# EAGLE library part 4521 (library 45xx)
24-stage FREQUENCY DIVIDER
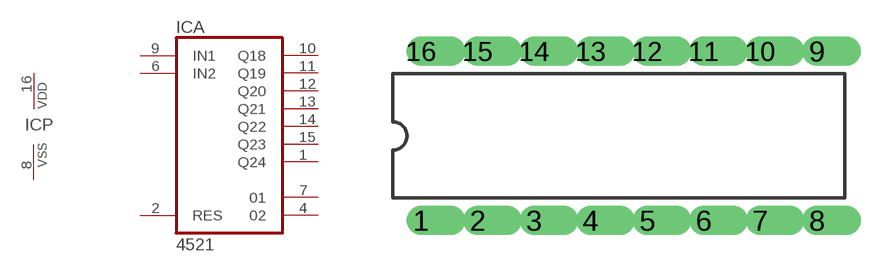
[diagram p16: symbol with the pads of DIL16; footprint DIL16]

Designator prefix IC; gates A=4521 P=PWRN

## 4521N  [DIL16]
1  A:Q24  out
2  A:RES  in
4  A:02  out
6  A:IN2  in
7  A:01  out
8  P:VSS  pwr
9  A:IN1  in
10  A:Q18  out
11  A:Q19  out
12  A:Q20  out
13  A:Q21  out
14  A:Q22  out
15  A:Q23  out
16  P:VDD  pwr

## Footprint DIL16 (pad centres in mm)
Dual In Line
drill 0.813 offset: 1 -8.89,-3.81; 2 -6.35,-3.81; 3 -3.81,-3.81; 4 -1.27,-3.81; 5 1.27,-3.81; 6 3.81,-3.81; 7 6.35,-3.81; 8 8.89,-3.81; 9 8.89,3.81; 10 6.35,3.81; 11 3.81,3.81; 12 1.27,3.81; 13 -1.27,3.81; 14 -3.81,3.81; 15 -6.35,3.81; 16 -8.89,3.81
